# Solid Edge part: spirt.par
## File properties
Username: Kasutaja
Author: Kasutaja
Template: Iso Metric Part.par
Last saved by: Kasutaja
Revision: 6
Application: Solid Edge
Accuracy: 0,990
Face Style: Model Default
Fill Style: Normal
Coef. of Thermal Exp: 0.0
Thermal Conductivity: 0.0
Specific Heat: 0.0
Modulus of Elasticity: 0.0
Poisson's Ratio: 0.0
Yield Stress: 0.0
Ultimate Stress: 0.0
Elongation: 0.0
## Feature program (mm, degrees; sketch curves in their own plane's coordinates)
sketch for "unnamed Protrusion 1" plane through (0, 0, 0) normal (1, 0, 0) x-axis (0, 1, 0)
  line (0, 51.7355) -> (-10, 51.7355)
  line (-10, 51.7355) -> (-10, 46.6905)
  arc centre (-15.0007, 46.713) radius 5.0008 from (-20, 46.8357) to (-10, 46.6905) ccw
  line (-25, 46.8357) -> (-20, 46.8357)
  line (-25, 46.8357) -> (-25, 41.7355)
  line (-25, 41.7355) -> (-25, 38.8928)
  line (-25, 38.8928) -> (0, 38.8928)
  line (0, 51.7355) -> (0, 38.8928)
extrude "unnamed Protrusion 1" add finite 5 symmetric
body pattern "unnamed BodyPattern 1"
pattern "unnamed Pattern 1"
sketch for "ExtrudedProtrusion_2" plane through (0, 0, 51.7355) normal (0, 0, 1) x-axis (0, 1, 0)
  circle centre (0, 0) radius 2.4
extrude "ExtrudedProtrusion_2" add finite 80 along -normal
sketch for "ExtrudedProtrusion_10" plane through (0, 0, 51.7355) normal (0, 0, 1) x-axis (0, 1, 0)
  circle centre (0, 0) radius 2.4
extrude "ExtrudedProtrusion_10" add finite 140 along -normal
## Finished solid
Body 1: solid body, 14 faces, 32 edges, 20 vertices.
  Faces by surface: plane 11, cylinder 3
  Edges by curve: line 26, circle 6
Bounding box of the edges (mm): 5.000 x 50.000 x 140.000, from (-2.5, -25, -88.2645) to (2.5, 25, 51.7355).
Cylindrical faces by radius (mm): R2.4 x1, R5.0008 x2
Planar faces by outward normal: +x 1, +y 2, +z 3, -x 1, -y 2, -z 2
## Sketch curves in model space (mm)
circle centre (0, 0, 51.7355) radius 2.4
line (0, -15.4827, 41.7355) -> (0, -14.5187, 41.7355)
line (0, -20, 46.8357) -> (0, -20, 46.5904)
arc centre (0, -15.0007, 46.713) radius 5.0008 from (0, -20, 46.8357) through (0, -14.9242, 41.7128) to (0, -10, 46.6905)
line (0, -10, 51.7355) -> (0, -10, 46.6905)
line (0, -25, 46.8357) -> (0, -20, 46.8357)
line (0, -25, 46.8357) -> (0, -25, 41.7355)
line (0, -25, 41.7355) -> (0, -25, 38.8928)
line (0, -25, 38.8928) -> (0, 0, 38.8928)
line (0, 0, 51.7355) -> (0, 0, 38.8928)
line (0, 0, 51.7355) -> (0, -10, 51.7355)
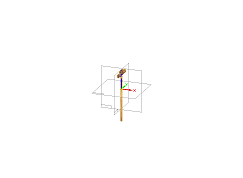
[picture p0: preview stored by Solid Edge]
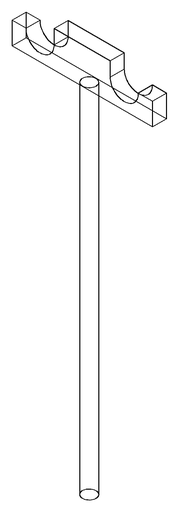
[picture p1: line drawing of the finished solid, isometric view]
